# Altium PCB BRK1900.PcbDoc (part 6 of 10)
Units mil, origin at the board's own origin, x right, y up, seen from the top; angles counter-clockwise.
Board outline 8858.27 x 5905.51 mil, 10 copper layers (L1-TOP, L2-GND, L3-SIG1, L4-GND, L5-PWR, L6-PWR, L7-GND, L8-SIG2, L9-GND, L10-BOT), stack 48.824 mil thick; 507 components, 607 nets, 2498 pads, 2210 vias.
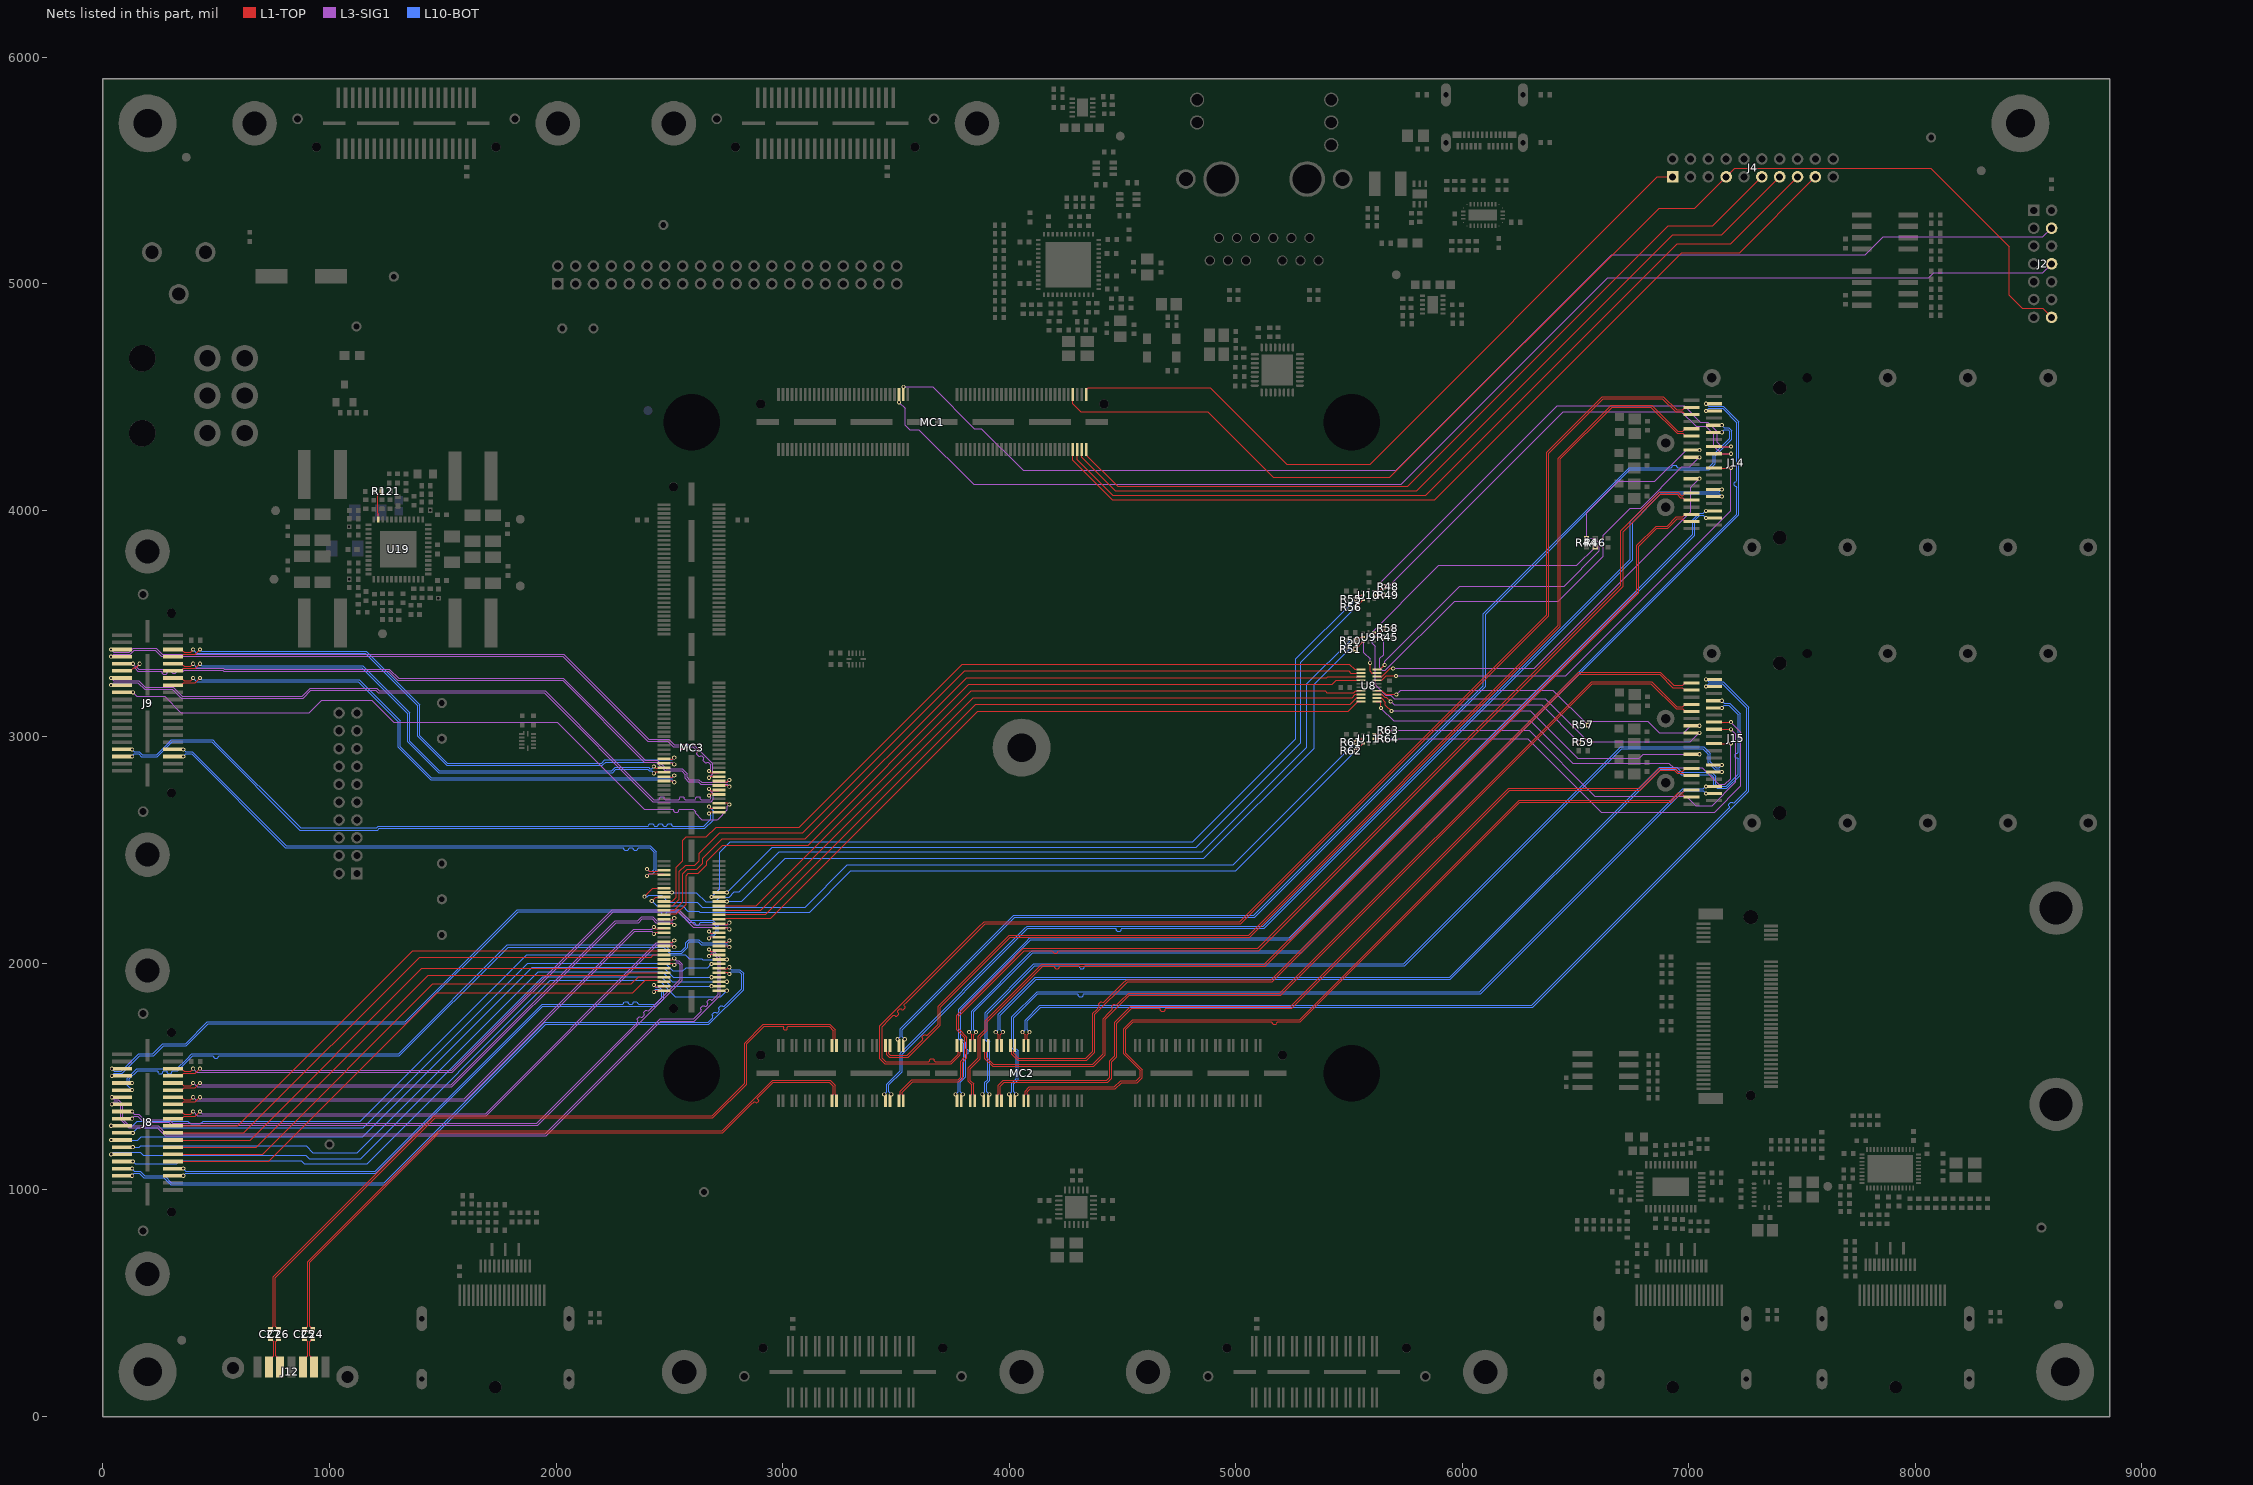
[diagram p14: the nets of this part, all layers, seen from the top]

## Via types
v1: diameter 18, hole 10, L1-TOP to L10-BOT, tented both sides, 2210 vias

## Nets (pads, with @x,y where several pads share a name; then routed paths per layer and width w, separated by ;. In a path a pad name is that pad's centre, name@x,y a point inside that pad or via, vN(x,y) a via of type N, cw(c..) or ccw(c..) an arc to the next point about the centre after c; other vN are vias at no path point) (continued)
PS_JTAG_TDO: J2.8 MC1.55 | length 5683.5
  L3-SIG1 w5: v1(3513.78,4477.42) 3541.29,4449.91 3541.29,4376.71 3561,4357 3602,4357 3843,4116 5731,4116 6643,5028 8060,5028 8081,5049 8562.74,5049 J2.8@8602,5088.26
PS_JTAG_TMS: J2.4 MC1.57 | length 5663.8
  L3-SIG1 w5: v1(3533.46,4545.42) 3662.58,4545.42 3847,4361 3878,4361 4062,4177 5709,4177 6660,5128 7780,5128 7859,5207 8563.26,5207 J2.4@8602,5245.74
PS_MODE0: J4.17 MC1.114 | length 3987.3
  L1-TOP w4.84: MC1.114@4281.5,4268.11 4281.5,4220.5 4454.76,4047.24 5877.95,4047.24 6968.5,5137.8 7224.41,5137.8 J4.17@7559.06,5472.44
PS_MODE1: J4.15 MC1.116 | length 3871.2
  L1-TOP w4.84: MC1.116@4301.18,4268.11 4301.18,4222.82 4457.07,4066.93 5838.58,4066.93 6948.82,5177.17 7185.04,5177.17 J4.15@7480.31,5472.44
PS_MODE2: J4.13 MC1.118 | length 3749.2
  L1-TOP w4.84: MC1.118@4320.87,4268.11 4320.87,4235.13 4469.39,4086.61 5799.21,4086.61 6929.13,5216.54 7145.67,5216.54 J4.13@7401.57,5472.44
PS_MODE3: J4.11 MC1.120 | length 3629
  L1-TOP w5: MC1.120@4340.55,4268.11 4340.55,4244.45 4478.7,4106.3 5759.84,4106.3 6909.45,5255.91 7106.3,5255.91 J4.11@7322.83,5472.44
PS_PROG_B: J4.1 MC1.119 | length 3277.6
  L1-TOP w5: MC1.119@4340.55,4511.42 4340.55,4532.55 4349,4541 4889,4541 5225.28,4204.72 5593.72,4204.72 6861.44,5472.44 J4.1@6929.13,5472.44
PS_SRST_B: J2.14 J4.7 MC1.113 | length 5459
  L1-TOP w4.84: MC1.113@4281.5,4511.42 4281.5,4470.5 4317.13,4434.87 4876.13,4434.87 5165.33,4145.67 5681.1,4145.67 6870.08,5334.65 7027.56,5334.65 J4.7@7165.35,5472.44 7202.91,5510 8069,5510 8415,5164 8415,4950 8473,4892 8562.04,4892 J2.14@8602,4852.04
QSFP1_INT_B: MC3.42 R51.1 U9.3 | length 3450.3
  L1-TOP w5: v1(5528.14,3387.65) 5529.51,3387.65 U9.3@5563.18,3421.32
  L10-BOT w5: v1(2754.08,2273.62) 2820.62,2273.62 3011,2464 4860,2464 5346,2950 5346,3233 5500.65,3387.65 v1(5528.14,3387.65)
QSFP1_INT_B_3V3: J14.28 R45.1 U9.6 | length 2042.6
  L1-TOP w5: U9.6@5610.82,3441 5611.17,3440.65 v1(5652.77,3440.65)
  L3-SIG1 w5: v1(5652.77,3440.65) 5652.77,3363.77 5637,3348 5637,3305 5647,3295 5661.47,3295 5966.47,3600 6425,3600 6623,3798 6623,3891 6742,4010 6788.3,4010 6970.33,4192.03 7005.29,4192.03 v1(7047.61,4234.35)
QSFP1_LP_MODE: MC3.36 U8.9 | length 3229
  L1-TOP w5: MC3.36@2720.08,2214.57 2722.51,2217 2925.66,2217 3852.5,3143.83 5505.83,3143.83 5533.88,3171.88 U8.9@5552.57,3171.88
QSFP1_LP_MODE_3V3: J14.31 U8.18 | length 1848.8
  L1-TOP w5: U8.18@5623.43,3266.37 5645.37,3266.37 5681.49,3302.49 v1(5695.42,3302.49)
  L3-SIG1 w5: v1(5695.42,3302.49) 6317.49,3302.49 7010,3995 7010,4102.25 v1(7047.61,4139.87)
QSFP1_MODPRS_B: MC3.40 U8.7 | length 3231.5
  L1-TOP w5: MC3.40@2720.08,2253.94 2883.86,2253.94 3832.81,3202.89 5396,3202.89 5402.89,3196 5522,3196 5529.38,3203.38 U8.7@5552.57,3203.38
QSFP1_MODPRS_B_3V3: J14.27 R44.1 U8.20 | length 2033.8
  L1-TOP w5: U8.20@5623.43,3297.87 5637.87,3297.87 v1(5658,3318)
  L3-SIG1 w5: v1(5658,3318) 5658,3335 5989,3666 6450,3666 6606,3822 6606,3855 6583.61,3877.39 v1(6549,3877.39) 6549,3989 6688,4128 6851,4128 6988.85,4265.85 v1(7047.61,4265.85)
QSFP1_MODSEL_B: MC3.38 U8.8 | length 3227.4
  L1-TOP w5: MC3.38@2720.08,2234.25 2903.54,2234.25 3842.65,3173.36 5514.05,3173.36 5528.32,3187.63 U8.8@5552.57,3187.63
QSFP1_MODSEL_B_3V3: R46.1 U8.19 | length 1372.3
  L1-TOP w5: v1(5594,3327) 5594,3289 5600.88,3282.12 U8.19@5623.43,3282.12
  L3-SIG1 w5: v1(5594,3327) 5594,3344 5566,3372 5566,3425.58 5897.42,3757 6505.98,3757 v1(6587,3838.02)
QSFP1_RESET_B: MC3.34 U8.10 | length 3230.7
  L1-TOP w5: MC3.34@2720.08,2194.88 2743.88,2194.88 2748,2199 2947.03,2199 3862.34,3114.31 5496.31,3114.31 5538.13,3156.13 U8.10@5552.57,3156.13
QSFP1_RESET_B_3V3: J14.9 U8.17 | length 2137
  L1-TOP w4.2: J14.9@7111.43,4187.11 v1(7186.43,4187.11)
  L1-TOP w5: U8.17@5623.43,3250.62 5645.62,3250.62 5664,3269 v1(5708,3269)
  L3-SIG1 w5: v1(5708,3269) 6458,3269 7186.43,3997.43 v1(7186.43,4187.11)
QSFP1_RX1N: J14.18 MC2.47 | length 5036.9
  L1-TOP w3.3: MC2.47@3848.43,1637.4 3848.43,1660.5 3843.08,1665.84 3843.08,1685.65 v1(3854.33,1696.9)
  L10-BOT w3.3: v1(3854.33,1696.9) 3843.08,1708.15 3843.08,1786.08 4105,2048 5289.73,2048 5290.81,2049.08 7222,3980.27 7222,4390.43 7153.1,4459.33 7087.68,4459.33 v1(7076.43,4470.57)
QSFP1_RX1P: J14.17 MC2.45 | length 5036.5
  L1-TOP w3.3: v1(3822.83,1696.9) 3834.08,1685.65 3834.08,1665.02 3828.74,1659.68 MC2.45@3828.74,1637.4
  L10-BOT w3.3: v1(3822.83,1696.9) 3834.08,1708.15 3834.08,1746.81 3834.08,1789.81 4091.52,2047.24 4101.27,2057 5286,2057 7213,3984 7213,4100.52 7213,4102.17 7208.94,4106.23 7205.06,4106.23 7201,4110.29 7201,4122.47 7205.06,4126.53 7208.94,4126.53 7213,4130.59 7213,4144 7213,4386.7 7149.37,4450.33 7087.68,4450.33 v1(7076.43,4439.08)
QSFP1_RX2N: J14.21 MC2.43 | length 5750.7
  L1-TOP w3.3: MC2.43@3789.37,1637.4 3789.37,1614.17 3784.03,1608.83 3784.03,1596.27 3745.54,1557.79 3451.09,1557.79 3430,1578.87 3430,1670 3430,1724 3867,2161 3890.2,2184.2 5018.84,2184.2 6373,3538.35 6373,4256.73 6618.97,4502.7 6887.88,4502.7 6947,4443.58 6973.71,4443.58 6984.96,4454.83 J14.21@7012.61,4454.83
QSFP1_RX2P: J14.22 MC2.41 | length 5749.5
  L1-TOP w3.3: MC2.41@3769.68,1637.4 3769.68,1614.34 3775.03,1609 3775.03,1600 3741.81,1566.79 3696,1566.79 3674.05,1566.79 3669.99,1570.85 3669.99,1574.73 3665.93,1578.79 3653.75,1578.79 3649.69,1574.73 3649.69,1570.85 3645.63,1566.79 3632,1566.79 3454.82,1566.79 3439,1582.6 3439,1673.73 3439,1720.27 3473.86,1755.14 3489.39,1770.66 3495.13,1770.66 3497.87,1767.91 3503.61,1767.91 3512.22,1776.53 3512.22,1782.27 3509.48,1785.01 3509.48,1790.75 3518.09,1799.37 3523.84,1799.37 3526.58,1796.62 3532.32,1796.62 3540.93,1805.23 3540.93,1810.98 3538.19,1813.72 3538.19,1819.46 3547.36,1828.64 3893.92,2175.2 5002.2,2175.2 5022.57,2175.2 6382,3534.63 6382,3555 6382,4253 6622.7,4493.7 6884.15,4493.7 6943.27,4434.58 6973.52,4434.58 6984.76,4423.33 J14.22@7012.61,4423.33
QSFP1_RX3N: J14.15 MC2.39 | length 5088.4
  L10-BOT w3.3: v1(3539.37,1665.4) 3528.12,1676.65 3528.12,1708 4024.85,2204.72 5084.45,2204.72 5755,2875.27 6103,3223.27 6103,3540.99 6740.71,4178.7 7090.73,4178.7 7093.36,4181.34 7118,4205.97 7118,4241.97 7191,4314.97 7191,4351.43 7177.59,4364.84 7157.68,4364.84 v1(7146.43,4376.09)
QSFP1_RX3P: J14.14 MC2.37 | length 5088
  L10-BOT w3.3: v1(3507.87,1665.4) 3519.12,1676.65 3519.12,1711.73 3989.39,2182 4021.12,2213.72 5080.72,2213.72 6094,3227 6094,3526.7 6094,3544.72 6736.98,4187.7 6755,4187.7 6922,4187.7 6923.65,4187.7 6927.71,4191.76 6927.71,4195.64 6931.77,4199.7 6943.95,4199.7 6948.01,4195.64 6948.01,4191.76 6952.07,4187.7 6975,4187.7 7087,4187.7 7109,4209.7 7109,4245.7 7182,4318.7 7182,4347.7 7173.86,4355.84 7157.68,4355.84 v1(7146.43,4344.59)
QSFP1_RX4N: J14.24 MC2.35 | length 5319.9
  L1-TOP w3.3: MC2.35@3474.41,1637.4 3474.41,1614.08 3469.07,1608.74 3469.07,1600.93 3475,1595 3551,1595 3599,1643 3619.38,1663.38 3619.38,1669.12 3616.64,1671.87 3616.64,1677.61 3625.25,1686.22 3630.99,1686.22 3633.74,1683.48 3639.48,1683.48 3655,1699 3687,1731 3687,1810.73 3970.27,2094 3991.57,2115.3 4001.41,2125.14 5058.21,2125.14 6425,3491.93 6425,4230.73 6658.97,4464.7 6837,4464.7 6952.61,4349.09 6973.03,4349.09 6984.28,4360.34 J14.24@7012.61,4360.34
QSFP1_RX4P: J14.25 MC2.33 | length 5320.3
  L1-TOP w3.3: MC2.33@3454.72,1637.4 3454.72,1614.54 3460.07,1609.19 3460.07,1597.21 3468.64,1588.64 3471.27,1586 3554.73,1586 3696,1727.27 3696,1807 4005.14,2116.14 5038.14,2116.14 5061.94,2116.14 6434,3488.2 6434,3512 6434,4227 6662.7,4455.7 6833.27,4455.7 6948.88,4340.09 6973.61,4340.09 6984.86,4328.84 J14.25@7012.61,4328.84
QSFP1_SCL: MC3.44 R55.1 U10.2 | length 3730.4
  L1-TOP w5: v1(5529.14,3608.65) 5545.5,3625 U10.2@5564.18,3625
  L10-BOT w5: v1(2686.08,2293.31) 2722,2329.23 2722,2491 2769,2538 4810,2538 5265,2993 5265,3344.5 v1(5529.14,3608.65)
QSFP1_SCL_3V3: J14.11 R48.1 U10.7 | length 2084.8
  L1-TOP w5: U10.7@5611.82,3644.68 5635.81,3644.68 v1(5653.77,3662.65) ; J14.11@7111.43,4250.1 v1(7186.43,4250.1)
  L3-SIG1 w5: v1(5653.77,3662.65) 5672.65,3662.65 6446,4436 6968,4436 7032.61,4371.39 7075.61,4371.39 7111.53,4335.47 7111.53,4283.47 7144.9,4250.1 v1(7186.43,4250.1)
QSFP1_SDA: MC3.46 R56.1 U10.3 | length 3554.2
  L1-TOP w5: v1(5529.14,3571.65) 5530.51,3571.65 U10.3@5564.18,3605.32
  L10-BOT w5: v1(2754.08,2312.99) 2954.09,2513 4827,2513 5288,2974 5288,3330.5 v1(5529.14,3571.65)
QSFP1_SDA_3V3: J14.12 R49.1 U10.6 | length 2156.9
  L1-TOP w5: U10.6@5611.82,3625 5612.17,3624.65 v1(5653.77,3624.65) ; J14.12@7111.43,4281.6 v1(7186.43,4281.6)
  L3-SIG1 w5: v1(5653.77,3624.65) 5632,3646.42 5632,3674 6419,4461 6980,4461 7051.78,4389.22 7084.36,4389.22 7127.06,4346.51 7127.06,4300.94 7146.4,4281.6 v1(7186.43,4281.6)
QSFP1_TX1N: J14.37 MC2.48 | length 4555.6
  L1-TOP w3.3: MC2.48@3848.43,1394.09 3848.43,1416.65 3843.08,1422 3843.08,1468.92 3829,1483 3829,1535.72 3873,1579.72 3873,1675.27 3903,1705.27 3903,1743 4148.19,1988.19 4175,1988.19 4196.95,1988.19 4201.01,1984.13 4201.01,1980.25 4205.07,1976.19 4217.25,1976.19 4221.31,1980.25 4221.31,1984.13 4225.37,1988.19 4250,1988.19 5108.19,1988.19 5130.84,1988.19 6779.14,3636.49 6779.14,3659.14 6779.14,3841.41 6859.73,3922 6908.3,3922 6948.44,3962.14 6972.56,3962.14 6983.81,3950.89 J14.37@7012.61,3950.89
QSFP1_TX1P: J14.36 MC2.46 | length 4556
  L1-TOP w3.3: MC2.46@3828.74,1394.09 3828.74,1416.63 3834.08,1421.97 3834.08,1465.19 3820,1479.27 3820,1539.45 3864,1583.45 3864,1679 3894,1709 3894,1746.73 4102.27,1955 4144.46,1997.19 5127.11,1997.19 6770.14,3640.21 6770.14,3845.14 6856,3931 6904.57,3931 6944.71,3971.14 6973.44,3971.14 6984.68,3982.39 J14.36@7012.61,3982.39
QSFP1_TX2N: J14.2 MC2.44 | length 4646.7
  L10-BOT w3.3: v1(3795.28,1422.09) 3784.03,1433.34 3784.03,1475.03 3808,1499 3808,1574.36 3808,1596.31 3812.06,1600.37 3815.94,1600.37 3820,1604.43 3820,1616.61 3815.94,1620.67 3812.06,1620.67 3808,1624.73 3808,1642.36 3808,1649.73 3787,1670.73 3787,1795 4096,2104 5239.73,2104 7027,3891.27 7027,3955.7 7049.18,3977.89 7065.19,3977.89 v1(7076.43,3966.64)
QSFP1_TX2P: J14.3 MC2.42 | length 4647.1
  L10-BOT w3.3: v1(3763.78,1422.09) 3775.03,1433.34 3775.03,1478.76 3799,1502.73 3799,1646 3778,1667 3778,1749.73 3778,1798.73 4074.89,2095.61 4092.27,2113 5236,2113 7018,3895 7018,3959.43 7045.46,3986.89 7065.19,3986.89 v1(7076.43,3998.13)
QSFP1_TX3N: J14.34 MC2.40 | length 4983.9
  L1-TOP w3.3: MC2.40@3533.46,1394.09 3533.46,1417.18 3528.12,1422.52 3528.12,1432 3574.12,1478 3778.85,1478 3794.72,1493.86 3794.72,1564.12 3814,1583.41 3814,1675 3778,1711 3778,1768 4067.09,2057.09 4169,2057.09 4190.95,2057.09 4195.01,2053.03 4195.01,2049.15 4199.07,2045.09 4211.25,2045.09 4215.31,2049.15 4215.31,2053.03 4219.37,2057.09 4238,2057.09 5088.09,2057.09 5101.31,2057.09 6710,3665.78 6710,3679 6710,3906.7 6874,4070.7 6949.2,4070.7 6963.27,4056.63 6973.07,4056.63 6984.32,4045.38 J14.34@7012.61,4045.38
QSFP1_TX3P: J14.33 MC2.38 | length 4984.3
  L1-TOP w3.3: MC2.38@3513.78,1394.09 3513.78,1416.58 3519.12,1421.93 3519.12,1435.73 3570.39,1487 3775.13,1487 3785.72,1497.59 3785.72,1567.85 3805,1587.14 3805,1671.27 3769,1707.27 3769,1771.73 4010.27,2013 4043.67,2046.4 4063.36,2066.09 5097.58,2066.09 6701,3669.5 6701,3910.43 6702.15,3911.58 6870.27,4079.7 6952.93,4079.7 6967,4065.63 6973.45,4065.63 6984.7,4076.87 J14.33@7012.61,4076.87
QSFP1_TX4N: J14.5 MC2.36 | length 4966.7
  L10-BOT w3.3: v1(3480.31,1422.09) 3469.07,1433.34 3469.07,1464.07 3528,1523 3528,1600 4083,2155 4448,2155 4469.95,2155 4474.01,2150.94 4474.01,2147.06 4478.07,2143 4490.25,2143 4494.31,2147.06 4494.31,2150.94 4498.37,2155 4520,2155 5125.73,2155 5810,2839.27 6751.97,3781.24 6751.97,3948.67 6875.67,4072.37 7135.19,4072.37 v1(7146.43,4061.13)
QSFP1_TX4P: J14.6 MC2.34 | length 4967.1
  L10-BOT w3.3: v1(3448.82,1422.09) 3460.07,1433.34 3460.07,1467.79 3519,1526.73 3519,1556.73 3519,1603.73 4069.94,2154.67 4079.27,2164 5122,2164 6742.97,3784.97 6742.97,3952.4 6871.95,4081.37 7135.19,4081.37 v1(7146.43,4092.62)
QSFP2_INT_B: MC3.45 R50.1 U9.2 | length 3717
  L1-TOP w5: v1(5528.14,3424.65) 5544.5,3441 U9.2@5563.18,3441
  L10-BOT w5: v1(2510.77,2312.99) 2620.01,2312.99 2661,2272 2702,2272 2723,2293 2764.64,2293 2787.14,2315.5 2808.5,2315.5 2986,2493 4853,2493 5315,2955 5315,3234 5505.65,3424.65 v1(5528.14,3424.65)
QSFP2_INT_B_3V3: J15.28 R58.1 U9.7 | length 1875.7
  L1-TOP w5: U9.7@5610.82,3460.68 5634.81,3460.68 v1(5652.77,3478.65)
  L3-SIG1 w5: v1(5652.77,3478.65) 5604,3429.87 5604,3413 5616,3401 5616,3230 5662,3184 5685,3184 5701,3168 6366,3168 6556,2978 7007.72,2978 v1(7047.61,3017.88)
QSFP2_LP_MODE: MC3.37 U8.3 | length 3588.7
  L1-TOP w5: MC3.37@2476.77,2234.25 2520.95,2234.25 2558.65,2271.95 2558.65,2395.65 2579.19,2416.19 2622.18,2416.19 2648.14,2442.15 2648.14,2464.14 2734,2550 3101.18,2550 3813.13,3261.94 5402,3261.94 5406.43,3266.37 U8.3@5552.57,3266.37
QSFP2_LP_MODE_3V3: J15.31 U8.12 | length 1549.4
  L1-TOP w5: U8.12@5623.43,3171.88 5642.31,3171.88 5661.41,3152.78 5661.41,3140.78 v1(5687.57,3114.62)
  L3-SIG1 w5: v1(5687.57,3114.62) 6301.38,3114.62 6511,2905 6781,2905 6799.39,2923.39 v1(7047.61,2923.39)
QSFP2_MODPRS_B: MC3.41 U8.1 | length 3649.8
  L1-TOP w5: MC3.41@2476.77,2273.62 2512.62,2273.62 2530.31,2291.31 2530.31,2424.77 2560,2454.47 2560,2544 2575,2559 2664,2559 2707,2602 3074.44,2602 3793.44,3321 5502,3321 5525.13,3297.87 U8.1@5552.57,3297.87
QSFP2_MODPRS_B_3V3: J15.27 R57.1 U8.14 | length 1542.7
  L1-TOP w5: U8.14@5623.43,3203.38 5645.81,3203.38 5661.57,3187.62 v1(5709.57,3187.62)
  L3-SIG1 w5: v1(5709.57,3187.62) 5728.94,3207 6400.39,3207 v1(6554.69,3052.7) 6570.98,3069 6820,3069 6870,3019 6978,3019 7008.38,3049.38 v1(7047.61,3049.38)
QSFP2_MODSEL_B: MC3.39 U8.2 | length 3601.8
  L1-TOP w5: MC3.39@2476.77,2253.94 2515.94,2253.94 2544.54,2282.54 2544.54,2406.49 2572.04,2434 2612.81,2434 2631.17,2452.36 2631.17,2486.17 2722,2577 3088.81,2577 3803.28,3291.47 5499.53,3291.47 5508.88,3282.12 U8.2@5552.57,3282.12
QSFP2_MODSEL_B_3V3: R59.1 U8.13 | length 979.3
  L1-TOP w5: U8.13@5623.43,3187.63 5645.56,3187.63 5657.57,3175.62 5665.57,3175.62 v1(5684.57,3156.62)
  L3-SIG1 w5: v1(5684.57,3156.62) 5700.19,3141 6351.02,3141 v1(6515.31,2976.7)
QSFP2_RESET_B: MC3.35 U8.4 | length 3587.8
  L1-TOP w5: MC3.35@2476.77,2214.57 2500.48,2214.57 2504.92,2219 2530.42,2219 2573.86,2262.44 2573.86,2387.86 2583.42,2397.42 2628.42,2397.42 2666.11,2435.11 2666.11,2451.11 2737,2522 3112.55,2522 3822.97,3232.42 5426,3232.42 5444.2,3250.62 U8.4@5552.57,3250.62
QSFP2_RESET_B_3V3: J15.9 U8.11 | length 1969.2
  L1-TOP w4.2: J15.9@7111.43,2970.64 v1(7186.43,2970.64)
  L1-TOP w5: U8.11@5623.43,3156.13 5637.05,3156.13 5641.51,3151.68 v1(5641.51,3127.19)
  L3-SIG1 w5: v1(5641.51,3127.19) 5697.69,3071 6301,3071 6488,2884 6913,2884 6933,2864 7059,2864 7133,2790 7160,2790 7186.43,2816.43 v1(7186.43,2970.64)
QSFP2_RX1N: J15.18 MC2.63 | length 4336.1
  L1-TOP w3.3: MC2.63@4084.65,1637.4 4084.65,1659.97 4079.3,1665.32 4079.3,1685.65 v1(4090.55,1696.9)
  L10-BOT w3.3: v1(4090.55,1696.9) 4079.3,1708.15 4079.3,1746.3 4139,1806 6310.73,1806 7265,2760.27 7265,3130.43 7228,3167.43 7152.57,3242.85 7087.67,3242.85 v1(7076.43,3254.1)
QSFP2_RX1P: J15.17 MC2.61 | length 4335.7
  L1-TOP w3.3: v1(4059.06,1696.9) 4070.3,1685.65 4070.3,1665.22 4064.96,1659.88 MC2.61@4064.96,1637.4
  L10-BOT w3.3: v1(4059.06,1696.9) 4070.3,1708.15 4070.3,1750.03 4135.27,1815 6307,1815 7179.17,2687.17 7180.33,2688.33 7180.33,2694.08 7177.59,2696.82 7177.59,2702.56 7186.2,2711.17 7191.94,2711.17 7194.69,2708.43 7200.43,2708.43 7208.5,2716.5 7256,2764 7256,3126.7 7148.85,3233.85 7087.67,3233.85 v1(7076.43,3222.61)
QSFP2_RX2N: J15.21 MC2.59 | length 3884.7
  L1-TOP w3.3: MC2.59@4025.59,1637.4 4025.59,1614.69 4020.25,1609.34 4020.25,1603 4041.25,1582 4339,1582 4369,1612 4369,1779.18 4386,1796.18 4393.91,1804.09 4398.29,1808.47 4398.29,1814.22 4395.55,1816.96 4395.55,1822.7 4404.16,1831.31 4409.9,1831.31 4412.65,1828.57 4418.39,1828.57 4433.91,1844.09 4501.82,1912 4518.95,1929.13 5157.48,1929.13 6514.05,3285.7 6875,3285.7 6933.59,3227.11 6973.41,3227.11 6984.65,3238.35 J15.21@7012.61,3238.35
QSFP2_RX2P: J15.22 MC2.57 | length 3885.1
  L1-TOP w3.3: MC2.57@4005.91,1637.4 4005.91,1614.78 4011.25,1609.43 4011.25,1599.27 4037.52,1573 4342.73,1573 4378,1608.27 4378,1775.46 4522.68,1920.13 5138.86,1920.13 5161.21,1920.13 6517.78,3276.7 6871.27,3276.7 6929.87,3218.11 6972.6,3218.11 6983.84,3206.86 J15.22@7012.61,3206.86
QSFP2_RX3N: J15.15 MC2.55 | length 4316.5
  L1-TOP w3.3: MC2.55@3966.54,1637.4 3965.42,1638.52 3965.42,1661.2 3961.19,1665.42 3961.19,1685.65 v1(3972.44,1696.9)
  L10-BOT w3.3: v1(3972.44,1696.9) 3961.19,1708.15 3961.19,1772.19 4119,1930 5948,1930 6875.64,2857.64 6942.64,2857.64 6966.27,2834 7100,2834 7111,2823 7111,2788.27 7126.27,2773 7168.73,2773 7227,2831.27 7227,3102.09 7180.73,3148.37 7157.67,3148.37 v1(7146.43,3159.61)
QSFP2_RX3P: J15.14 MC2.53 | length 4316.1
  L1-TOP w3.3: v1(3940.94,1696.9) 3952.19,1685.65 3952.19,1664.91 3946.85,1659.57 MC2.53@3946.85,1637.4
  L10-BOT w3.3: v1(3940.94,1696.9) 3952.19,1708.15 3952.19,1751.92 3952.19,1775.92 4115.27,1939 4139.27,1939 5944.27,1939 6869.27,2864 6871.91,2866.64 6946.36,2866.64 6949,2864 6970,2843 7103.73,2843 7106.36,2840.36 7120,2826.73 7120,2792 7130,2782 7165,2782 7218,2835 7218,2901.33 7218,2902.98 7213.94,2907.04 7210.06,2907.04 7206,2911.1 7206,2923.28 7210.06,2927.34 7213.94,2927.34 7218,2931.4 7218,2942 7218,3098.37 7177,3139.37 7157.67,3139.37 v1(7146.43,3128.12)
QSFP2_RX4N: J15.24 MC2.51 | length 4034.4
  L1-TOP w3.3: MC2.51@3907.48,1637.4 3907.48,1614.16 3902.14,1608.82 3902.14,1583.86 3931,1555 4369,1555 4415,1601 4415,1739.73 4415,1756.73 4442.64,1784.36 4455.52,1797.25 4455.52,1802.99 4452.78,1805.73 4452.78,1811.47 4461.39,1820.09 4467.13,1820.09 4469.87,1817.34 4475.61,1817.34 4491.14,1832.86 4527.27,1869 4544.27,1869 4635.27,1869 5195.77,1869 6570.94,3244.17 6580.78,3244.17 6836.53,3244.17 6948.08,3132.62 6972.9,3132.62 6984.14,3143.87 J15.24@7012.61,3143.87
QSFP2_RX4P: J15.25 MC2.49 | length 4034.9
  L1-TOP w3.3: MC2.49@3887.8,1637.4 3887.8,1614.46 3893.14,1609.11 3893.14,1580.13 3927.27,1546 4372.73,1546 4424,1597.27 4424,1753 4531,1860 5158.73,1860 5186.77,1860 5199.5,1860 6574.67,3235.17 6832.8,3235.17 6944.36,3123.62 6972.83,3123.62 6984.08,3112.37 J15.25@7012.61,3112.37
QSFP2_SCL: MC3.47 R61.1 U11.2 | length 3607.6
  L1-TOP w4: v1(2390.08,2294.67) 2428.08,2332.68 MC3.47@2476.77,2332.68
  L1-TOP w5: v1(5529.14,2975.65) 5545.5,2992 U11.2@5564.18,2992
  L10-BOT w5: v1(2390.08,2294.67) 2403.67,2294.67 2409,2300 2466,2300 2495,2271 2624,2271 2646,2249 3100,2249 3286,2435 4988.5,2435 v1(5529.14,2975.65)
QSFP2_SCL_3V3: J15.11 R63.1 U11.7 | length 2100.5
  L1-TOP w5: U11.7@5611.82,3011.68 5635.81,3011.68 v1(5653.77,3029.65) ; J15.11@7111.43,3033.63 v1(7186.43,3033.63)
  L3-SIG1 w5: v1(5653.77,3029.65) 6295.35,3029.65 6586,2739 6990,2739 7032,2697 7103,2697 7208,2802 7208,3012.06 v1(7186.43,3033.63)
QSFP2_SDA: MC3.43 R62.1 U11.3 | length 3531.7
  L1-TOP w4: v1(2422.73,2275.73) 2440.31,2293.31 MC3.43@2476.77,2293.31
  L1-TOP w5: v1(5529.14,2938.65) 5530.51,2938.65 U11.3@5564.18,2972.32
  L10-BOT w5: v1(2422.73,2275.73) 2444.47,2254 2559,2254 2582,2231 2630,2231 2634,2227 3119,2227 3302,2410 5000.5,2410 v1(5529.14,2938.65)
QSFP2_SDA_3V3: J15.12 R64.1 U11.6 | length 2174.6
  L1-TOP w5: U11.6@5611.82,2992 5612.17,2991.65 v1(5653.77,2991.65) ; J15.12@7111.43,3065.13 v1(7186.43,3065.13)
  L3-SIG1 w5: v1(5653.77,2991.65) 6289.35,2991.65 6613,2668 7114,2668 7230,2784 7230,3021.55 v1(7186.43,3065.13)
QSFP2_TX1N: J15.37 MC2.64 | length 3765.1
  L1-TOP w3.3: MC2.64@4084.65,1394.09 4084.65,1416.73 4079.3,1422.07 4079.3,1433 4092.54,1446.24 4468.97,1446.24 4496.73,1474 4565.73,1474 4588,1496.27 4588,1531.73 4515,1604.73 4515,1709 4548.97,1742.97 5136,1742.97 5157.95,1742.97 5162.01,1738.91 5162.01,1735.03 5166.07,1730.97 5178.25,1730.97 5182.31,1735.03 5182.31,1738.91 5186.37,1742.97 5205,1742.97 5286.28,1742.97 6255.01,2711.7 6924,2711.7 6957.96,2745.67 6974.04,2745.67 6982,2737.7 7009.32,2737.7 J15.37@7012.61,2734.42
QSFP2_TX1P: J15.36 MC2.62 | length 3765.6
  L1-TOP w3.3: MC2.62@4064.96,1394.09 4064.96,1417.16 4070.3,1422.5 4070.3,1436.73 4088.82,1455.24 4465.24,1455.24 4493,1483 4562,1483 4579,1500 4579,1528 4514,1593 4506,1601 4506,1712.73 4514,1720.73 4545.24,1751.97 4586.24,1751.97 5282.55,1751.97 6251.28,2720.7 6270.97,2720.7 6402.7,2720.7 6920.27,2720.7 6954.24,2754.67 6973.96,2754.67 6985.21,2765.91 J15.36@7012.61,2765.91
QSFP2_TX2N: J15.2 MC2.60 | length 3848
  L10-BOT w3.3: v1(4031.5,1422.09) 4020.25,1433.34 4020.25,1468 4040,1487.75 4040,1613.73 4021,1632.73 4021,1760 4127,1866 4280,1866 4301.95,1866 4306.01,1861.94 4306.01,1858.06 4310.07,1854 4322.25,1854 4326.31,1858.06 4326.31,1861.94 4330.37,1866 4359,1866 6081.73,1866 6977.14,2761.41 7065.18,2761.41 v1(7076.43,2750.17)
QSFP2_TX2P: J15.3 MC2.58 | length 3848.4
  L10-BOT w3.3: v1(4000,1422.09) 4011.25,1433.34 4011.25,1471.73 4031,1491.48 4031,1610 4012,1629 4012,1756.73 4012,1763.73 4123.27,1875 4130.27,1875 6078,1875 6973.41,2770.41 7065.18,2770.41 v1(7076.43,2781.66)
QSFP2_TX3N: J15.34 MC2.56 | length 3849.6
  L1-TOP w3.3: MC2.56@3966.54,1394.09 3966.54,1417.12 3961.19,1422.46 3961.19,1458.19 3978,1475 4435.73,1475 4454,1493.27 4454,1567 4475,1588 4475,1736 4541.02,1802.02 4642,1802.02 4663.95,1802.02 4668.01,1797.96 4668.01,1794.08 4672.07,1790.02 4684.25,1790.02 4688.31,1794.08 4688.31,1797.96 4692.37,1802.02 4711,1802.02 5246.91,1802.02 6209.88,2765 6785.73,2765 6873.48,2852.75 6936.22,2852.75 6948.82,2840.15 6973.02,2840.15 6984.27,2828.91 J15.34@7012.61,2828.91
QSFP2_TX3P: J15.33 MC2.54 | length 3850
  L1-TOP w3.3: MC2.54@3946.85,1394.09 3946.85,1416.94 3952.19,1422.28 3952.19,1461.92 3974.27,1484 4432,1484 4445,1497 4445,1570.73 4466,1591.73 4466,1699.73 4466,1708.73 4466,1739.73 4537.3,1811.02 4568.3,1811.02 4577.3,1811.02 5243.18,1811.02 6206.15,2774 6309.27,2774 6782,2774 6869.75,2861.75 6939.95,2861.75 6952.55,2849.15 6973.45,2849.15 6984.7,2860.4 J15.33@7012.61,2860.4
QSFP2_TX4N: J15.5 MC2.52 | length 4179
  L10-BOT w3.3: v1(3913.39,1422.09) 3902.14,1433.34 3902.14,1471 3915,1483.86 3915,1655.73 3903,1667.73 3903,1779 4113,1989 4285,1989 4306.95,1989 4311.01,1984.94 4311.01,1981.06 4315.07,1977 4327.25,1977 4331.31,1981.06 4331.31,1984.94 4335.37,1989 4350,1989 5745.73,1989 6704.73,2948 7063,2948 7087,2924 7087,2886.17 7117.27,2855.9 7135.18,2855.9 v1(7146.43,2844.65)
QSFP2_TX4P: J15.6 MC2.50 | length 4179.4
  L10-BOT w3.3: v1(3881.89,1422.09) 3893.14,1433.34 3893.14,1474.73 3906,1487.59 3906,1652 3894,1664 3894,1757.73 3894,1782.73 4109.27,1998 4134.27,1998 5742,1998 6701,2957 7066.73,2957 7069.36,2954.36 7096,2927.73 7096,2889.9 7121,2864.9 7135.18,2864.9 v1(7146.43,2876.15)
SATA_TXA+: C24.2 MC2.18 | length 3038.3
  L1-TOP w3.3: C24.2@926,384.16 912.5,397.66 912.5,680.5 1485,1253 2736.73,1253 2776.73,1293 2861.36,1377.64 2874.06,1390.33 2877.51,1390.33 2883.63,1384.21 2887.09,1384.21 2895.16,1392.28 2895.16,1395.74 2889.04,1401.85 2889.04,1405.31 2894.36,1410.64 2959.73,1476 3206.84,1476 3223.85,1458.99 3223.85,1421.74 3218.5,1416.4 MC2.18@3218.5,1394.09
SATA_TXA+_C: C24.1 J12.2 | length 139.8
  L1-TOP w3.3: C24.1@926,344 911.98,329.98 911.98,268.74 932.48,248.24 J12.2@932.48,218.5
SATA_TXA-: C25.2 MC2.20 | length 3046.8
  L1-TOP w3.3: C25.2@890,384.08 903.5,397.58 903.5,684.23 1481.27,1262 2733,1262 2941,1470 2956,1485 3205.73,1485 3210.57,1485 3232.85,1462.72 3232.85,1457.88 3232.85,1437.73 3232.85,1422.45 3238.19,1417.11 MC2.20@3238.19,1394.09
SATA_TXA-_C: C25.1 J12.3 | length 139.3
  L1-TOP w3.3: J12.3@882.48,218.5 882.48,247.59 902.98,268.09 902.98,330.94 C25.1@890,343.92
SATA_TXB+: C27.2 MC2.19 | length 3366
  L1-TOP w3.3: C27.2@739.15,384.08 752.65,397.58 752.65,617.38 1462.27,1327 2689,1327 2833,1471 2833,1648.73 2915.03,1730.76 3209.07,1730.76 3232.85,1706.98 3232.85,1665.72 3238.19,1660.38 MC2.19@3238.19,1637.4
SATA_TXB+_C: C27.1 J12.6 | length 139.6
  L1-TOP w3.3: J12.6@732.48,218.5 732.48,248.3 752.98,268.8 752.98,330.09 C27.1@739.15,343.92
SATA_TXB-: C26.2 MC2.17 | length 3357.5
  L1-TOP w3.3: C26.2@775.15,384.08 761.65,397.58 761.65,613.65 1466,1318 2681.73,1318 2692.73,1318 2842,1467.27 2842,1478.27 2842,1645 2918.76,1721.76 2985,1721.76 3002.95,1721.76 3005.4,1719.31 3005.4,1710.66 3007.84,1708.21 3019.25,1708.21 3021.7,1710.66 3021.7,1719.31 3024.14,1721.76 3033,1721.76 3205.35,1721.76 3223.85,1703.25 3223.85,1665.67 3218.5,1660.32 MC2.17@3218.5,1637.4
SATA_TXB-_C: C26.1 J12.5 | length 139.4
  L1-TOP w3.3: C26.1@775.15,343.92 761.98,330.75 761.98,268.56 782.48,248.06 J12.5@782.48,218.5
SUPPLY_1_CE: R121.1 U19.23 | length 134
  L1-TOP w5: U19.23@1215,3959.53 1215,3985.82 1213.29,3987.53 1213.29,4067.21 1221.3,4075.22 1223.26,4075.22 1230.61,4082.56 R121.1@1230.61,4084.53
SZG_PORTA_C2P_CLKN: J8.36 MC3.3 | length 2578.3
  L1-TOP w5.25: v1@2431.77,1903.54 2434.07,1903.54 2440.35,1897.26 2474.43,1897.26 MC3.3@2476.77,1899.61
  L10-BOT w3.3: v1@354.36,1064 364.62,1074.26 1185.99,1074.26 1205.1,1074.26 1941.86,1811.02 2440.94,1811.02 2475,1845.08 2475,1875.99 2456.73,1894.26 2441.05,1894.26 v1@2431.77,1903.54
  other v1: 354.36,1063.01 2431.77,1904.54
SZG_PORTA_C2P_CLKP: J8.34 MC3.1 | length 2577.5
  L1-TOP w5.25: v1@2431.77,1875.98 2434.07,1875.98 2440.35,1882.26 2474.43,1882.26 MC3.1@2476.77,1879.92
  L10-BOT w3.3: v1@354.36,1093.52 364.62,1083.26 1201.37,1083.26 1938.13,1820.02 2293.78,1820.02 2295.43,1820.02 2299.49,1824.08 2299.49,1827.96 2303.55,1832.02 2315.73,1832.02 2319.79,1827.96 2319.79,1824.08 2323.85,1820.02 2336.03,1820.02 2340.09,1824.08 2340.09,1827.96 2344.15,1832.02 2356.33,1832.02 2360.39,1827.96 2360.39,1824.08 2364.45,1820.02 2381,1820.02 2437.22,1820.02 2466,1848.81 2466,1872.26 2453,1885.26 2441.05,1885.26 v1@2431.77,1875.98
  other v1: 354.36,1094.51 2431.77,1874.88
SZG_PORTA_P2C_CLKN: J8.35 MC3.12 | length 3275.4
  L1-TOP w5.25: MC3.12@2720.08,1978.35 2722.42,1976 2756.5,1976 2762.78,1982.28 v1@2765.08,1982.28
  L10-BOT w3.3: v1@128.76,1064 139.02,1074.26 160.74,1074.26 181,1054 268,1054 295,1027 298.82,1023.18 1245.9,1023.18 1249.73,1027 1955.01,1732.28 2675.28,1732.28 2828,1885 2828,1956.73 2811.72,1973 2774.36,1973 v1@2765.08,1982.28
  other v1: 128.76,1063.01 2765.08,1983.28
SZG_PORTA_P2C_CLKP: J8.33 MC3.10 | length 3274.6
  L1-TOP w5.25: MC3.10@2720.08,1958.66 2722.42,1961 2756.5,1961 2762.78,1954.72 v1@2765.08,1954.72
  L10-BOT w3.3: v1@128.76,1093.52 139.02,1083.26 164.47,1083.26 184.73,1063 271.73,1063 302.55,1032.18 1242.18,1032.18 1604,1394 1951.28,1741.28 2671.56,1741.28 2691.64,1761.36 2692.8,1762.53 2692.8,1768.27 2690.06,1771.02 2690.06,1776.76 2698.67,1785.37 2704.41,1785.37 2707.16,1782.63 2712.9,1782.63 2721.51,1791.24 2721.51,1796.98 2718.77,1799.72 2718.77,1805.47 2727.38,1814.08 2733.12,1814.08 2735.87,1811.34 2741.61,1811.34 2751.14,1820.86 2819,1888.73 2819,1953 2808,1964 2774.36,1964 v1@2765.08,1954.72
  other v1: 128.76,1094.51 2765.08,1953.62
SZG_PORTA_S0_D0P: J8.5 MC3.26 | length 3132.5
  L1-TOP w5.25: v1@2675.08,2112.21 2677.38,2112.21 2683.66,2118.48 2717.74,2118.48 MC3.26@2720.08,2116.14
  L10-BOT w3.3: v1@39.35,1534.52 49.61,1524.26 81.26,1524.26 158,1601 220,1601 265,1646 365,1646 461,1742 1334,1742 1829,2237 2539.73,2237 2542.06,2237 2589.06,2190 2692.73,2190 2713.36,2169.36 2716,2166.73 2716,2140.76 2696.73,2121.48 2684.36,2121.48 v1@2675.08,2112.21
  other v1: 39.35,1535.51 2675.08,2111.11
SZG_PORTA_S1_D1P: J8.6 MC3.30 | length 2845.3
  L1-TOP w3.3: J8.6@309.65,1535.51 346.54,1535.51 357.79,1524.26 386.98,1524.26 v1(398.23,1535.51)
  L1-TOP w5.25: MC3.30@2720.08,2155.51 2722.42,2157.85 2756.5,2157.85 2762.78,2151.58 v1@2765.08,2151.58
  L3-SIG1 w3.15: v1(398.23,1535.51) 414.75,1519 1542.73,1519 2251.53,2227.8 2538.67,2227.8 2605.61,2160.85 2755.8,2160.85 v1@2765.08,2151.58
  other v1: 2765.08,2150.48
SZG_PORTA_S2_D0N: J8.7 MC3.28 | length 3131.7
  L1-TOP w5.25: v1@2675.08,2139.76 2677.38,2139.76 2683.66,2133.48 2717.74,2133.48 MC3.28@2720.08,2135.83
  L10-BOT w3.3: v1@39.35,1505 49.61,1515.26 84.99,1515.26 161.73,1592 223.73,1592 268.73,1637 368.73,1637 464.73,1733 1337.73,1733 1832.73,2228 2441,2228 2462.95,2228 2467.01,2223.94 2467.01,2220.06 2471.07,2216 2483.25,2216 2487.31,2220.06 2487.31,2223.94 2491.37,2228 2502,2228 2538.33,2228 2585.33,2181 2588,2181 2609.95,2181 2614.01,2176.94 2614.01,2173.06 2618.07,2169 2630.25,2169 2634.31,2173.06 2634.31,2176.94 2638.37,2181 2647,2181 2689,2181 2707,2163 2707,2144.48 2693,2130.48 2684.36,2130.48 v1@2675.08,2139.76
  other v1: 39.35,1504.01 2675.08,2140.76
SZG_PORTA_S3_D1N: J8.8 MC3.32 | length 2845.3
  L1-TOP w3.3: J8.8@309.65,1504.01 346.4,1504.01 357.65,1515.26 407.51,1515.26 v1@427.76,1535.51
  L1-TOP w5.25: MC3.32@2720.08,2175.2 2722.42,2172.85 2756.5,2172.85 2762.78,2179.13 v1@2765.08,2179.13
  L3-SIG1 w3.15: v1@427.76,1535.51 435.27,1528 1539,1528 2247.8,2236.8 2533.93,2236.8 2540.19,2236.8 2542.4,2236.8 2609.34,2169.85 2755.8,2169.85 v1@2765.08,2179.13
  other v1: 428.26,1535.51 2765.08,2180.13
SZG_PORTA_S4_D2P: J8.9 MC3.22 | length 3055.8
  L1-TOP w5.25: MC3.22@2720.08,2076.77 2722.42,2079.11 2756.5,2079.11 2762.78,2072.83 v1@2765.08,2072.83
  L10-BOT w3.3: v1@128.76,1471.52 117,1483.28 117,1490 153,1526 217,1526 238.95,1526 243.01,1521.94 243.01,1518.06 247.07,1514 259.25,1514 263.31,1518.06 263.31,1521.94 267.37,1526 279.55,1526 283.61,1521.94 283.61,1518.06 287.67,1514 299.85,1514 303.91,1518.06 303.91,1521.94 307.97,1526 313,1526 329.73,1526 396.73,1593 463,1593 484.95,1593 489.01,1588.94 489.01,1585.06 493.07,1581 505.25,1581 509.31,1585.06 509.31,1588.94 513.37,1593 521,1593 1308.73,1593 1788.27,2072.54 2475.36,2072.54 2501.9,2046 2555.73,2046 2580.7,2070.97 2580.7,2087.59 2589.11,2096 2627,2096 2640.89,2082.11 2755.8,2082.11 v1@2765.08,2072.83
  other v1: 128.76,1472.51 2765.08,2071.74
SZG_PORTA_S5_D3P: J8.10 MC3.31 | length 2595.3
  L1-TOP w3.3: J8.10@309.65,1472.51 346.28,1472.51 357.53,1461.26 386.98,1461.26 v1(398.23,1472.51)
  L1-TOP w5.25: MC3.31@2476.77,2175.2 2479.11,2177.54 2513.19,2177.54 2519.47,2171.26 v1@2521.77,2171.26
  L3-SIG1 w3.15: v1(398.23,1472.51) 415.75,1455 1540.73,1455 2266.27,2180.54 2365,2180.54 2381.46,2197 2423.81,2197 2440.27,2180.54 2512.49,2180.54 v1@2521.77,2171.26
  other v1: 2521.77,2170.16
SZG_PORTA_S6_D2N: J8.11 MC3.24 | length 3060.5
  L1-TOP w5.25: MC3.24@2720.08,2096.46 2722.42,2094.11 2756.5,2094.11 2762.78,2100.39 v1@2765.08,2100.39
  L10-BOT w3.3: v1@128.76,1442 108,1462.76 108,1493.73 149.27,1535 326,1535 369,1578 393,1602 1305,1602 1784.54,2081.54 2465.46,2081.54 2479.09,2081.54 2505.63,2055 2552,2055 2571.7,2074.7 2571.7,2091.32 2572,2091.61 2585.39,2105 2630.73,2105 2644.61,2091.11 2755.8,2091.11 v1@2765.08,2100.39
  other v1: 128.76,1441.01 2765.08,2101.39
SZG_PORTA_S7_D3N: J8.12 MC3.33 | length 2595.3
  L1-TOP w3.3: J8.12@309.65,1441.01 346.57,1441.01 357.82,1452.26 407.51,1452.26 v1@427.76,1472.51
  L1-TOP w5.25: MC3.33@2476.77,2194.88 2479.11,2192.54 2513.19,2192.54 2519.47,2198.82 v1@2521.77,2198.82
  L3-SIG1 w3.15: v1@427.76,1472.51 436.27,1464 1537,1464 2262.54,2189.54 2361.27,2189.54 2377.73,2206 2427.54,2206 2444,2189.54 2512.49,2189.54 v1@2521.77,2198.82
  other v1: 428.26,1472.51 2521.77,2199.82
SZG_PORTA_S8_D4P: J8.13 MC3.18 | length 3325.3
  L1-TOP w5.25: v1@2675.08,2033.46 2677.38,2033.46 2683.66,2039.74 2717.74,2039.74 MC3.18@2720.08,2037.4
  L3-SIG1 w3.15: v1@39.35,1408.52 49.61,1398.26 67.73,1398.26 87,1378.99 87,1313 117,1283 243.73,1283 278.73,1248 1511,1248 1952.27,1248 2459.27,1755 2497.27,1755 2542.29,1755 2576,1755 2607,1755 2641,1789 2642.11,1790.11 2642.11,1795.81 2639.33,1798.6 2639.33,1804.3 2647.88,1812.85 2653.58,1812.85 2656.36,1810.06 2662.06,1810.06 2670.61,1818.61 2670.61,1824.31 2667.82,1827.1 2667.82,1832.79 2676.37,1841.34 2682.07,1841.34 2684.86,1838.56 2690.56,1838.56 2699.5,1847.5 2716,1864 2716,2020.74 2694,2042.74 2684.36,2042.74 v1@2675.08,2033.46
  other v1: 39.35,1409.51 2675.08,2032.36
SZG_PORTA_S9_D5P: J8.14 MC3.27 | length 2500.6
  L1-TOP w3.3: J8.14@309.65,1409.51 346.64,1409.51 357.89,1398.26 386.98,1398.26 v1(398.23,1409.51)
  L1-TOP w5.25: v1@2431.77,2131.89 2434.07,2131.89 2440.35,2138.17 2474.43,2138.17 MC3.27@2476.77,2135.83
  L3-SIG1 w3.15: v1(398.23,1409.51) 414.75,1393 1598.73,1393 2346.9,2141.17 2422.49,2141.17 v1@2431.77,2131.89
  other v1: 2431.77,2130.79
SZG_PORTA_S10_D4N: J8.15 MC3.20 | length 3326
  L1-TOP w5.25: v1@2675.08,2061.02 2677.38,2061.02 2683.66,2054.74 2717.74,2054.74 MC3.20@2720.08,2057.09
  L3-SIG1 w3.15: v1@39.35,1379 49.61,1389.26 64,1389.26 78,1375.26 78,1309.27 113.27,1274 240,1274 275,1239 1514.73,1239 1956,1239 2463,1746 2610.73,1746 2725,1860.27 2725,2024.47 2697.73,2051.74 2684.36,2051.74 v1@2675.08,2061.02
  other v1: 39.35,1378.01 2675.08,2062.02
SZG_PORTA_S11_D5N: J8.16 MC3.29 | length 2500.6
  L1-TOP w3.3: J8.16@309.65,1378.01 346.51,1378.01 357.76,1389.26 407.51,1389.26 v1@427.76,1409.51
  L1-TOP w5.25: v1@2431.77,2159.45 2434.07,2159.45 2440.35,2153.17 2474.43,2153.17 MC3.29@2476.77,2155.51
  L3-SIG1 w3.15: v1@427.76,1409.51 435.27,1402 1595,1402 2343.17,2150.17 2422.49,2150.17 v1@2431.77,2159.45
  other v1: 428.26,1409.51 2431.77,2160.45
SZG_PORTA_S12_D6P: J8.17 MC3.13 | length 2879.9
  L1-TOP w5.25: MC3.13@2476.77,1998.03 2479.11,2000.37 2513.19,2000.37 2519.47,1994.09 v1@2521.77,1994.09
  L3-SIG1 w3.15: v1@128.76,1345.52 139.02,1335.26 157.73,1335.26 183.99,1309 293.73,1309 307.08,1295.65 953.82,1295.65 1606.48,1295.65 1914.65,1295.65 2360.31,1741.31 2361.42,1742.42 2361.42,1748.12 2358.63,1750.91 2358.63,1756.6 2367.18,1765.15 2372.88,1765.15 2375.67,1762.37 2381.37,1762.37 2389.92,1770.92 2389.92,1776.62 2387.13,1779.4 2387.13,1785.1 2395.68,1793.65 2401.38,1793.65 2404.16,1790.86 2409.86,1790.86 2417,1798 2549,1930 2549,1993.37 2539,2003.37 2531.05,2003.37 v1@2521.77,1994.09
  other v1: 128.76,1346.51 2521.77,1992.99
SZG_PORTA_S13_D7P: J8.18 MC3.21 | length 2593.9
  L1-TOP w3.3: J8.18@309.65,1346.51 312.44,1343.72 349.69,1343.72 358.15,1335.26 386.98,1335.26 v1(398.23,1346.51)
  L1-TOP w5.25: MC3.21@2476.77,2076.77 2479.11,2079.11 2513.19,2079.11 2519.47,2072.83 v1@2521.77,2072.83
  L3-SIG1 w3.15: v1(398.23,1346.51) 416.75,1328 1692.73,1328 2446.84,2082.11 2512.49,2082.11 v1@2521.77,2072.83
  other v1: 2521.77,2071.73
SZG_PORTA_S14_D6N: J8.19 MC3.15 | length 2880.6
  L1-TOP w5.25: MC3.15@2476.77,2017.72 2479.11,2015.37 2513.19,2015.37 2519.47,2021.65 v1@2521.77,2021.65
  L3-SIG1 w3.15: v1@128.76,1316 139.02,1326.26 154,1326.26 180.26,1300 290,1300 303.35,1286.65 957.55,1286.65 1602.75,1286.65 1918.38,1286.65 2558,1926.27 2558,1997.1 2542.73,2012.37 2531.05,2012.37 v1@2521.77,2021.65
  other v1: 128.76,1315.01 2521.77,2022.65
SZG_PORTA_S15_D7N: J8.20 MC3.23 | length 2593.9
  L1-TOP w3.3: J8.20@309.65,1315.01 346.56,1315.01 357.81,1326.26 407.51,1326.26 v1@427.76,1346.51
  L1-TOP w5.25: MC3.23@2476.77,2096.46 2479.11,2094.11 2513.19,2094.11 2519.47,2100.39 v1@2521.77,2100.39
  L3-SIG1 w3.15: v1@427.76,1346.51 437.27,1337 1689,1337 2443.11,2091.11 2512.49,2091.11 v1@2521.77,2100.39
  other v1: 428.26,1346.51 2521.77,2101.39
SZG_PORTA_S16: J8.21 MC3.16 | length 3050.1
  L10-BOT w4.55: v1(36.05,1283.51) 131.51,1283.51 152,1304 375,1304 386.47,1292.53 430.53,1292.53 442,1304 1136,1304 1870.3,2038.3 2570.89,2038.3 2588.19,2021 2643,2021 2648,2016 2752.36,2016 v1(2754.08,2017.72)
SZG_PORTA_S17: J8.22 MC3.19 | length 2487.5
  L1-TOP w4.55: J8.22@309.65,1283.51 594.54,1283.51 1368.11,2057.09 2080.09,2057.09 MC3.19@2476.77,2057.09
SZG_PORTA_S18: J8.23 MC3.14 | length 2891.2
  L10-BOT w4.55: v1(132.05,1252.01) 154.04,1274 1149,1274 1876,2001 2482,2001 2516,1967 2560,1967 2574,1981 2669.05,1981 v1(2686.08,1998.03)
SZG_PORTA_S19: J8.24 MC3.17 | length 2492.4
  L1-TOP w4.55: J8.24@309.65,1252.01 622.09,1252.01 1397.64,2027.56 2419.56,2027.56 2429.4,2037.4 MC3.17@2476.77,2037.4
SZG_PORTA_S20: J8.25 MC3.8 | length 2984.1
  L10-BOT w4.55: v1(36.05,1220.51) 154.51,1220.51 169,1235 1146,1235 1894,1983 2474.15,1983 2518.17,1938.98 v1(2686.08,1938.98)
SZG_PORTA_S21: J8.26 MC3.11 | length 2481
  L1-TOP w4.55: J8.26@309.65,1220.51 649.65,1220.51 1407.48,1978.35 2112.35,1978.35 MC3.11@2476.77,1978.35
SZG_PORTA_S22: J8.27 MC3.6 | length 2986.4
  L10-BOT w4.55: v1(132.05,1189.01) 160.01,1189.01 166,1195 897,1195 927,1165 1123,1165 1922,1964 2468.68,1964 2513.39,1919.29 v1(2754.08,1919.29)
SZG_PORTA_S23: J8.28 MC3.9 | length 2485.9
  L1-TOP w4.55: J8.28@309.65,1189.01 677.2,1189.01 1437.01,1948.82 2312.82,1948.82 2322.66,1958.66 MC3.9@2476.77,1958.66
SZG_PORTA_S24: J8.29 MC3.4 | length 3015.7
  L10-BOT w4.55: v1(36.05,1157.51) 45.54,1167 165,1167 178,1154 896,1154 911,1139 1139,1139 1942,1942 2464.84,1942 2507.23,1899.61 v1(2686.08,1899.61)
SZG_PORTA_S25: J8.30 MC3.7 | length 2493.3
  L1-TOP w4.55: J8.30@309.65,1157.51 704.76,1157.51 1456.69,1909.45 2332.45,1909.45 2365,1942 2473.75,1942 MC3.7@2476.77,1938.98
SZG_PORTA_S26: J8.31 MC3.2 | length 3012.2
  L10-BOT w4.55: v1(132.05,1126.01) 142.06,1116 326,1116 339,1129 875,1129 888,1116 1166,1116 1975,1925 2456.27,1925 2527.27,1854 2728.16,1854 v1(2754.08,1879.92)
SZG_PORTA_S27: J8.32 MC3.5 | length 2500.4
  L1-TOP w4.55: J8.32@309.65,1126.01 732.31,1126.01 1476.38,1870.08 2338.08,1870.08 2393,1925 2448.69,1925 2454.4,1919.29 MC3.5@2476.77,1919.29
SZG_PORTB_C2P_CLKN: J9.36 MC3.55 | length 2488.9
  L1-TOP w3.3: v1(2401.77,2416.35) 2412.05,2406.08 2448.53,2406.08 2453.88,2411.42 MC3.55@2476.77,2411.42
  L10-BOT w3.3: v1@354.36,2914.39 364.62,2924.66 391,2924.66 804.66,2511 2274,2511 2295.95,2511 2300.01,2506.94 2300.01,2503.06 2304.07,2499 2316.25,2499 2320.31,2503.06 2320.31,2506.94 2324.37,2511 2336.55,2511 2340.61,2506.94 2340.61,2503.06 2344.67,2499 2356.85,2499 2360.91,2503.06 2360.91,2506.94 2364.97,2511 2392,2511 2413,2511 2434.03,2489.97 2434.03,2416.26 2423.85,2406.08 2412.05,2406.08 v1(2401.77,2416.35)
  other v1: 354.36,2913.41
SZG_PORTB_C2P_CLKP: J9.34 MC3.53 | length 2489.8
  L1-TOP w3.3: v1(2401.77,2386.7) 2412.15,2397.08 2448.91,2397.08 2450.46,2395.52 2472.98,2395.52 MC3.53@2476.77,2391.73
  L10-BOT w3.3: v1@354.36,2943.92 364.62,2933.66 394.73,2933.66 808.38,2520 2416.73,2520 2443.03,2493.7 2443.03,2412.53 2427.58,2397.08 2412.15,2397.08 v1(2401.77,2386.7)
  other v1: 354.36,2944.91
SZG_PORTB_P2C_CLKN: J9.35 MC3.64 | length 2893.4
  L1-TOP w5.25: v1@2675.08,2690.95 2677.38,2690.95 2683.66,2684.67 2717.74,2684.67 MC3.64@2720.08,2687.01
  L10-BOT w3.3: v1@128.76,2914.39 139.02,2924.66 157,2924.66 168.66,2913 240.73,2913 305.73,2978 480,2978 869,2589 1212,2589 1219,2596 2655.73,2596 2693,2633.27 2693,2673.02 v1@2675.08,2690.95
  other v1: 2675.08,2691.95 128.76,2913.41
SZG_PORTB_P2C_CLKP: J9.33 MC3.62 | length 2890.6
  L1-TOP w5.25: v1@2675.08,2663.39 2677.38,2663.39 2683.66,2669.67 2717.74,2669.67 MC3.62@2720.08,2667.32
  L10-BOT w3.3: v1@128.76,2943.92 139.02,2933.66 160.73,2933.66 172.38,2922 237,2922 288,2973 302,2987 483.73,2987 497.73,2973 872.73,2598 1208.27,2598 1215.27,2605 2404.61,2605 2406.26,2605 2410.32,2609.06 2410.32,2612.94 2414.38,2617 2426.56,2617 2430.62,2612.94 2430.62,2609.06 2434.68,2605 2446.86,2605 2450.92,2609.06 2450.92,2612.94 2454.98,2617 2467.16,2617 2471.22,2612.94 2471.22,2609.06 2475.28,2605 2487.46,2605 2491.52,2609.06 2491.52,2612.94 2495.58,2617 2507.76,2617 2511.82,2612.94 2511.82,2609.06 2515.88,2605 2534,2605 2652,2605 2684,2637 2684,2654.46 v1@2675.08,2663.39
  other v1: 2675.08,2662.29 128.76,2944.91
SZG_PORTB_S0_D0P: J9.5 MC3.78 | length 2995.6
  L1-TOP w5.25: v1@2675.08,2820.87 2677.38,2820.87 2683.66,2827.15 2717.74,2827.15 MC3.78@2720.08,2824.8
  L3-SIG1 w3.15: v1(35.97,3385.91) 47.22,3374.66 116.66,3374.66 134,3392 234.73,3392 261.25,3365.48 2033.44,3365.48 2038.92,3360 2150.54,3248.39 2408.92,2990 2497,2990 2521,2966 2607.73,2966 2691.92,2881.8 2691.92,2837.71 v1@2675.08,2820.87
  other v1: 2675.08,2819.77
SZG_PORTB_S1_D1P: J9.6 MC3.83 | length 2570.6
  L1-TOP w3.3: J9.6@309.65,3385.91 346.64,3385.91 357.89,3374.66 386.98,3374.66 v1(398.23,3385.91)
  L1-TOP w5.25: MC3.83@2476.77,2883.86 2479.11,2886.2 2513.19,2886.2 2519.47,2879.92 v1@2521.77,2879.92
  L10-BOT w3.3: v1(398.23,3385.91) 415.14,3369 1158.56,3369 1390,3137.56 1390,3002 1513,2879 1516.82,2875.18 2204.98,2875.18 2208.8,2879 2219,2889.2 2512.49,2889.2 v1@2521.77,2879.92
  other v1: 2521.77,2878.82
SZG_PORTB_S2_D0N: J9.7 MC3.80 | length 2993.1
  L1-TOP w5.25: v1@2675.08,2848.43 2677.38,2848.43 2683.66,2842.15 2717.74,2842.15 MC3.80@2720.08,2844.49
  L3-SIG1 w3.15: v1(35.97,3354.41) 47.22,3365.66 120.38,3365.66 137.73,3383 231,3383 257.52,3356.48 2029.72,3356.48 2405.2,2981 2493.27,2981 2517.27,2957 2524.14,2957 2545.86,2957 2549.89,2952.97 2549.89,2949.03 2553.92,2945 2566.01,2945 2570.04,2949.03 2570.04,2952.97 2574.07,2957 2589,2957 2604,2957 2609,2952 2624.36,2936.64 2624.36,2930.94 2621.58,2928.15 2621.58,2922.45 2630.13,2913.9 2635.82,2913.9 2638.61,2916.69 2644.31,2916.69 2652.86,2908.14 2652.86,2902.44 2650.07,2899.66 2650.07,2893.96 2658.62,2885.41 2664.32,2885.41 2667.11,2888.19 2672.81,2888.19 2682.92,2878.08 2682.92,2856.27 v1@2675.08,2848.43
  other v1: 2675.08,2849.43
SZG_PORTB_S3_D1N: J9.8 MC3.85 | length 2570.6
  L1-TOP w3.3: J9.8@309.65,3354.41 346.51,3354.41 357.76,3365.66 407.51,3365.66 v1@427.76,3385.9
  L1-TOP w5.25: MC3.85@2476.77,2903.54 2479.11,2901.2 2513.19,2901.2 2519.47,2907.48 v1@2521.77,2907.48
  L10-BOT w3.3: v1@427.76,3385.9 435.66,3378 1115.73,3378 1162.29,3378 1399,3141.29 1399,3094.73 1399,3005.73 1520.55,2884.18 2201.25,2884.18 2215.27,2898.2 2512.49,2898.2 v1@2521.77,2907.48
  other v1: 2521.77,2908.48 428.26,3385.9
SZG_PORTB_S4_D2P: J9.9 MC3.74 | length 2950.9
  L1-TOP w5.25: MC3.74@2720.08,2785.43 2722.42,2787.78 2756.5,2787.78 2762.78,2781.5 v1@2765.08,2781.5
  L3-SIG1 w3.15: v1(132.13,3322.91) 142.4,3312.64 142.4,3302.27 154.67,3290 237.09,3290 258.82,3290 262.85,3285.97 262.85,3280 266.88,3275.97 278.97,3275.97 283,3280 283,3285.97 287.03,3290 299.12,3290 303.15,3285.97 303.15,3285.67 307.18,3281.64 319.27,3281.64 323.3,3285.67 323.3,3285.97 327.33,3290 342.09,3290 351,3290 355.22,3290 359.22,3294 528.27,3294 532.27,3290 1261,3290 1301,3250 2029.27,3250 2390.27,2889 2443.16,2889 2482.16,2850 2554,2850 2570,2834 2570,2817.27 2584.27,2803 2627,2803 2639.22,2790.78 2755.79,2790.78 v1@2765.08,2781.5
  other v1: 2765.08,2780.4
SZG_PORTB_S5_D3P: J9.10 MC3.79 | length 2464.3
  L1-TOP w3.3: J9.10@309.65,3322.91 346.64,3322.91 357.89,3311.66 386.98,3311.66 v1(398.23,3322.91)
  L1-TOP w5.25: v1@2431.77,2840.55 2434.07,2840.55 2440.35,2846.83 2474.43,2846.83 MC3.79@2476.77,2844.49
  L10-BOT w3.3: v1(398.23,3322.91) 415.14,3306 1142.82,3306 1346,3102.82 1346,2978 1481.46,2842.54 2250.7,2842.54 2264.44,2856.27 2404.6,2856.27 2411.04,2849.83 2422.49,2849.83 v1@2431.77,2840.55
  other v1: 2431.77,2839.45
SZG_PORTB_S6_D2N: J9.11 MC3.76 | length 3000.7
  L1-TOP w3.3: J9.11@84.05,3291.41 120.41,3291.41 135,3306 144.76,3306 v1@161.66,3322.9
  L1-TOP w5.25: MC3.76@2720.08,2805.12 2722.42,2802.78 2756.5,2802.78 2762.78,2809.06 v1@2765.08,2809.06
  L3-SIG1 w3.15: v1@161.66,3322.9 151.4,3312.64 151.4,3306 158.4,3299 351.49,3299 355.49,3303 361,3303 532,3303 536,3299 1264.73,3299 1304.73,3259 2033,3259 2090,3202 2394,2898 2446.89,2898 2485.89,2859 2557.73,2859 2579,2837.73 2579,2821 2588,2812 2630.73,2812 2642.95,2799.78 2755.8,2799.78 v1@2765.08,2809.06
  other v1: 2765.08,2810.06 162.16,3322.9
SZG_PORTB_S7_D3N: J9.12 MC3.81 | length 2464.3
  L1-TOP w3.3: J9.12@309.65,3291.41 346.51,3291.41 357.76,3302.66 407.51,3302.66 v1@427.76,3322.9
  L1-TOP w5.25: v1@2431.77,2868.11 2434.07,2868.11 2440.35,2861.83 2474.43,2861.83 MC3.81@2476.77,2864.17
  L10-BOT w3.3: v1@427.76,3322.9 435.66,3315 1146.55,3315 1355,3106.55 1355,2981.73 1485.19,2851.54 2246.98,2851.54 2260.71,2865.27 2404.73,2865.27 2408.33,2865.27 2414.76,2858.83 2422.49,2858.83 v1@2431.77,2868.11
  other v1: 2431.77,2869.11 428.26,3322.9
SZG_PORTB_S8_D4P: J9.13 MC3.70 | length 3010.1
  L1-TOP w5.25: v1@2675.08,2742.13 2677.38,2742.13 2683.66,2748.41 2717.74,2748.41 MC3.70@2720.08,2746.06
  L3-SIG1 w3.15: v1(35.97,3259.91) 47.22,3248.66 158.07,3248.66 187.73,3219 310.73,3219 349.36,3180.36 880.36,3180.36 914,3214 1208.73,3214 1219.73,3203 1951.73,3203 2097.61,3057.12 2111.73,3043 2203.73,2951 2431.03,2723.7 2453,2723.7 2454.58,2723.7 2458.61,2727.73 2458.61,2731.67 2462.64,2735.7 2474.73,2735.7 2478.76,2731.67 2478.76,2727.73 2482.79,2723.7 2500,2723.7 2539.58,2723.7 2541.15,2723.7 2545.18,2727.73 2545.18,2731.67 2549.21,2735.7 2561.3,2735.7 2565.33,2731.67 2565.33,2727.73 2569.36,2723.7 2588,2723.7 2612,2723.7 2613.58,2723.7 2617.61,2727.73 2617.61,2731.67 2621.64,2735.7 2633.73,2735.7 2637.76,2731.67 2637.76,2727.73 2641.79,2723.7 2653,2723.7 2680.7,2723.7 2683.63,2726.63 2683.63,2733.57 v1@2675.08,2742.13
  other v1: 2675.08,2741.03
SZG_PORTB_S9_D5P: J9.14 MC3.75 | length 2526.3
  L1-TOP w3.3: J9.14@309.65,3259.91 346.64,3259.91 357.89,3248.66 386.98,3248.66 v1(398.23,3259.91)
  L1-TOP w5.25: MC3.75@2476.77,2805.12 2479.11,2807.46 2513.19,2807.46 2519.47,2801.18 v1@2521.77,2801.18
  L10-BOT w3.3: v1(398.23,3259.91) 415.14,3243 1127.08,3243 1303,3067.08 1303,2954 1446.54,2810.46 1746.46,2810.46 2512.49,2810.46 v1@2521.77,2801.18
  other v1: 2521.77,2800.08
SZG_PORTB_S10_D4N: J9.15 MC3.72 | length 3014.6
  L1-TOP w5.25: v1@2675.08,2769.69 2677.38,2769.69 2683.66,2763.41 2717.74,2763.41 MC3.72@2720.08,2765.75
  L3-SIG1 w3.15: v1(35.97,3228.41) 47.22,3239.66 154.34,3239.66 184,3210 307,3210 343,3174 345.64,3171.36 884.09,3171.36 886.73,3174 917.73,3205 1205,3205 1216,3194 1948,3194 2427.3,2714.7 2684.43,2714.7 2695,2725.27 2695,2749.76 v1@2675.08,2769.69
  other v1: 2675.08,2770.69
SZG_PORTB_S11_D5N: J9.16 MC3.77 | length 2526.3
  L1-TOP w3.3: J9.16@309.65,3228.41 346.51,3228.41 357.76,3239.66 407.51,3239.66 v1@427.76,3259.9
  L1-TOP w5.25: MC3.77@2476.77,2824.8 2479.11,2822.46 2513.19,2822.46 2519.47,2828.74 v1@2521.77,2828.74
  L10-BOT w3.3: v1@427.76,3259.9 435.66,3252 1129.73,3252 1130.81,3252 1312,3070.81 1312,3069.73 1312,2957.73 1450.27,2819.46 1742.73,2819.46 2512.49,2819.46 v1@2521.77,2828.74
  other v1: 2521.77,2829.74 428.26,3259.9
SZG_PORTB_S12_D6P: J9.17 MC3.66 | length 3015.1
  L1-TOP w5.25: MC3.66@2720.08,2706.69 2722.42,2709.04 2756.5,2709.04 2762.78,2702.76 v1@2765.08,2702.76
  L3-SIG1 w3.15: v1(132.13,3196.91) 150.04,3179 273,3179 342,3110 344.64,3107.36 911.09,3107.36 913.73,3110 965.73,3162 1186,3162 1284,3064 2005.37,3064 2389.69,2679.68 2495,2679.68 2516.73,2679.68 2520.76,2675.65 2520.76,2671.71 2524.79,2667.68 2536.88,2667.68 2540.91,2671.71 2540.91,2675.65 2544.94,2679.68 2555,2679.68 2606.22,2679.68 2616,2669.9 2616,2663.27 2641.64,2637.64 2644.27,2635 2712.73,2635 2715.36,2637.64 2756,2678.27 2756,2693.68 v1@2765.08,2702.76
  other v1: 2765.08,2701.66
